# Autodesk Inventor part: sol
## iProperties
Shininess: 64.0
Length Units: 11269
Angle Units: 11279
Time Units: 11290
Mass Units: 11283
Length Display Precision: 3
Angle Display Precision: 2
Compacted: True
Part Number: sol
Document SubType Name: Modeling
Created: 2005-04
Material: Par défaut
Designer: thchene
Density: 0.0
Volumn: 0.0
Area: 0.0
PropertySet Name: Model Information
Control State: 0
Master: False
Checked Out: False
Author: thchene
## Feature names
1. Extrusion1
